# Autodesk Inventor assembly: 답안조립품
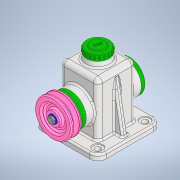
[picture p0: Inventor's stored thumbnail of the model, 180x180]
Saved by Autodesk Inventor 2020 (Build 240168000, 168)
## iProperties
Created: 2021-07
Part Number: 답안조립품
Document SubType Name: Assembly
Designer: Owner
Author: Owner
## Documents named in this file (14)
- C:\Users\Owner\Desktop\710715V1001\답안조립품.iam
- C:\Users\Owner\Desktop\710715V1001\본체.ipt
- C:\Users\Owner\Desktop\710715V1001\V-벨트풀리.ipt
- C:\Users\Owner\Desktop\710715V1001\뒤커버.ipt
- C:\Users\Owner\Desktop\710715V1001\멈춤링 15 x 1.ipt
- C:\Users\Owner\Desktop\710715V1001\베어링 15 x 35 x 11.ipt
- C:\Users\Owner\Desktop\710715V1001\볼트 M4 x 10.ipt
- C:\Users\Owner\Desktop\710715V1001\볼트 M6 x 12.ipt
- C:\Users\Owner\Desktop\710715V1001\상부캡.ipt
- C:\Users\Owner\Desktop\710715V1001\앞커버.ipt
- C:\Users\Owner\Desktop\710715V1001\오일실 15 25 7.ipt
- C:\Users\Owner\Desktop\710715V1001\와셔.ipt
- C:\Users\Owner\Desktop\710715V1001\축.ipt
- C:\Users\Owner\Desktop\710715V1001\키 5 x 5 x 14.ipt
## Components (1 placed, 1 different names)
1. V-벨트풀리:1
